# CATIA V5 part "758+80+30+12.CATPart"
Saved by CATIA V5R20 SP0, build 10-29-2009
Part number: 758+80+30+12
Revision: TUTTO
Definition: NON CONOSCIUTO
Nomenclature: 758+80+30+12
Bounding box of the stored display mesh (mm): x -40 to 40, y 0 to 30, z -40 to 40
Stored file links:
  C:\Users\Utente\Desktop\758+80+30+12.CATPart
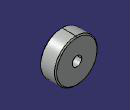
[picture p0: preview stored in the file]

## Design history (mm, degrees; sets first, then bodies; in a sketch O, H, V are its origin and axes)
Set1
  DatumSurface1 "FACE1"
  DatumSurface2 "FACE2"
  DatumSurface3 "FACE3"
  DatumSurface4 "FACE4"
  DatumSurface5 "FACE5"
  DatumSurface6 "FACE6"
  DatumSurface7 "SURF7"
  DatumSurface8 "SURF8"
  DatumSurface9 "SURF9"
  DatumSurface10 "FACE7"
  DatumSurface11 "FACE8"
Body1 (main body)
